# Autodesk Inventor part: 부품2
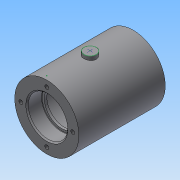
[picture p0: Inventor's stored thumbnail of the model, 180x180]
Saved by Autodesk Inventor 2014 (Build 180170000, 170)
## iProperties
Created: 2020-07
Part Number: 부품2
Material: 일반
Document SubType Name: Modeling
Designer: net
Density: 1 g/cm^3
Appearance: 기본값
Author: net
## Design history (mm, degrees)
sketch "스케치1"
  geometry: L1 (0, 0)-(70, 0); L2 (0, 0)-(0, 26); L3 (0, 26)-(70, 26); L4 (70, 26)-(70, 0)
  constraints: 8 end point, 3 perpendicular, 1 horizontal
  dimensions: "d0" = 70 distance of L1.start L1.end; "d1" = 52 diameter of L3 L1
revolve "회전1" sketch "스케치1" stored, may be unused: angle "d2" = 90 deg
sketch "스케치2"
  geometry: L1 (0, -26)-(0, 26) reference; L2 (0, 26)-(70, 26) reference; L3 (70, 26)-(70, -26) reference; L4 (70, -26)-(0, -26) reference; L5 (0, 0)-(70, 0); L6 (0, 0)-(0, 16); L7 (0, 16)-(11.7, 16); L8 (12, 15.7)-(12, 14); L9 (12, 14)-(14, 14); L10 (14, 14)-(14, 18); L11 (17, 21)-(53, 21); L12 (56, 18)-(56, 14); L13 (56, 14)-(58, 14); L14 (58, 14)-(58, 15.7); L15 (58.3, 16)-(70, 16); L16 (70, 0)-(70, 16); A1 r 3 centre (17, 18) between (17, 21) and (14, 18); A2 r 3 centre (53, 18) between (56, 18) and (53, 21); A3 r 0.3 centre (11.7, 15.7) between (12, 15.7) and (11.7, 16); A4 r 0.3 centre (58.3, 15.7) between (58.3, 16) and (58, 15.7); 2 further points
  constraints: 24 end point, 8 point on circle, 8 tangent, 6 parallel, 6 point on line, 4 centre point, 3 perpendicular, 2 equal radius, 1 collinear, 1 midpoint
  dimensions: "d3" = 32 diameter of L7 L5; "d4" = 28 diameter of L9 L5; "d5" = 32 diameter of L15 L5; "d6" = 28 diameter of L13 L5; "d7" = 42 diameter of L11 L5; "d8" = 12 distance of L6.end point (12, 16); "d9" = 12 distance of point (58, 16) L15.end; "d10" = 2 distance of L8.end L9.end; "d11" = 2 distance of L12.end L13.end; "d12" = 3 radius of A1; "d13" = 0.3 radius of A3
revolve "회전2" sketch "스케치2" stored, may be unused: angle "d14" = 90 deg
chamfer "모따기1" distance "d15" = 1; stored, may be unused: second distance "d16" = 2, angle "d17" = 45 deg
node "작업 평면1"
sketch "스케치3"
  geometry: C1 r 5 at (0, 35); 1 further point
  constraints: 1 centre point, 1 vertical alignment
  dimensions: "d19" = 10 diameter of C1; "d20" = 35 distance of C1.centre point (0, 0)
extrude "돌출1" join sketch "스케치3" stored distance "d21" = 10; taper "d22" = 0 deg
sketch "스케치4"
  geometry: C1 r 26 at (0, 0) reference; 1 further point
  constraints: 1 vertical alignment
  dimensions: "d23" = 21 distance of C1.centre point (0, 21)
hole "구멍1" sketch "스케치4" at (0, 21) diameter "d24" = 3.242; stored, may be unused: countersink angle "d28" = 90 deg, drill point angle "d30" = 118 deg; dims "d25" = 8, "d26" = 4, "d27" = 2, "d29" = 10
node "작업 평면2"
sketch "스케치5"
  geometry: C1 r 5 at (0, 0) reference; 2 further points
  constraints: 1 coincident
node "솔리드1"
pattern_circular "원형 패턴1" dims angle "d32" = 360 deg
mirror "대칭1"
node "절단 모서리 투영1"
other parameters: "d18" = 29
